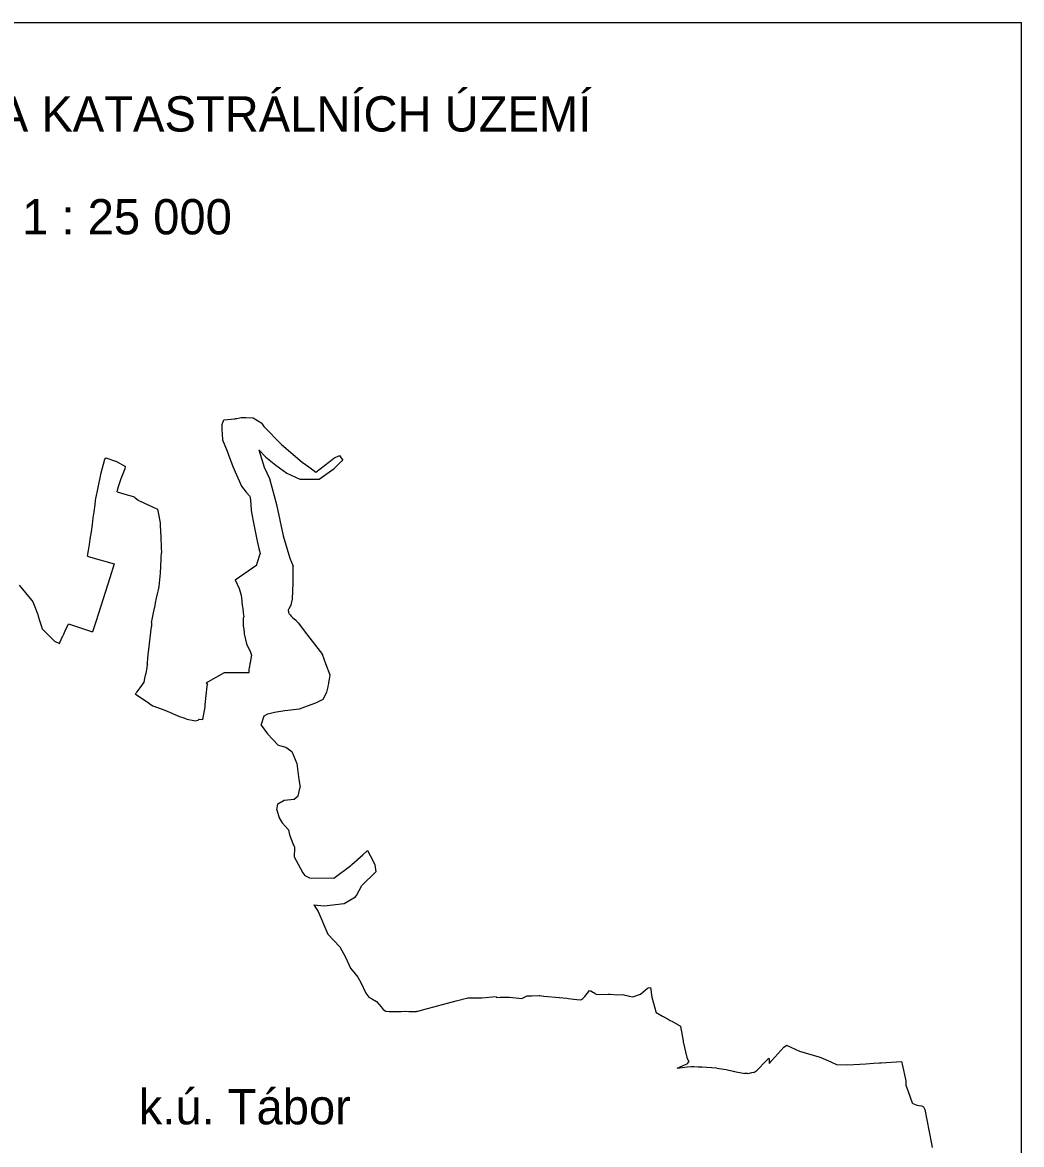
# Model space of a CAD drawing. Extents: x -738519 to -733269, y -1123734 to -1116309.
# Drawn here: x -736104 to -733269, y -1119491 to -1116309 of the extents above; entities that cross this region are included whole.
import ezdxf

# ---------------------------------------------------------------- set-up
doc = ezdxf.new("R2010")
doc.units = 0
doc.layers.add('Implicitní', color=7, linetype='Continuous')
doc.layers.add('Vrstva 13', color=7, linetype='Continuous')

msp = doc.modelspace()

# ---------------------------------------------------------------- linework, layer by layer
at = {"layer": 'Implicitní'}
for p in [(-738519, -1116308.5), (-733269, -1123733.5)]:
    msp.add_line(p, (-733269, -1116308.5), dxfattribs=at)
at = {"layer": 'Vrstva 13'}
for p, q in [((-735538, -1117449.6), (-735536.3, -1117445.8)), ((-735536.3, -1117445.8), (-735531.8, -1117435.8)), ((-735531.8, -1117435.8), (-735500.6, -1117432.4)), ((-735500.6, -1117432.4), (-735498.8, -1117432.2)), ((-735498.8, -1117432.2), (-735495.5, -1117431.5)), ((-735495.5, -1117431.5), (-735482.6, -1117428.8)), ((-735482.6, -1117428.8), (-735469.8, -1117429.1)), ((-735469.8, -1117429.1), (-735448.8, -1117429.6)), ((-735448.8, -1117429.6), (-735424.7, -1117445.2)), ((-735424.7, -1117445.2), (-735423.9, -1117445.7)), ((-735423.9, -1117445.7), (-735418.9, -1117454.7)), ((-735538, -1117449.6), (-735537.4, -1117462.1)), ((-735537.4, -1117462.1), (-735536.7, -1117476.9)), ((-735536.7, -1117476.9), (-735536.2, -1117491.2)), ((-735418.9, -1117454.7), (-735368.5, -1117505.7)), ((-735536.2, -1117491.2), (-735536.1, -1117492.6)), ((-735536.1, -1117492.6), (-735522.6, -1117524.5)), ((-735368.5, -1117505.7), (-735309.8, -1117556.1)), ((-735522.6, -1117524.5), (-735518.6, -1117535.3)), ((-735518.6, -1117535.3), (-735506.5, -1117567.8)), ((-735432.7, -1117520.9), (-735413, -1117541.5)), ((-735432.7, -1117520.9), (-735418.1, -1117569.6)), ((-735413, -1117541.5), (-735384.9, -1117564.7)), ((-735220.3, -1117544.8), (-735203.6, -1117536.7)), ((-735203.6, -1117536.7), (-735199.9, -1117542.2)), ((-735199.9, -1117542.2), (-735194.6, -1117549.8)), ((-735880, -1117586.3), (-735870.1, -1117546.9)), ((-735870.1, -1117546.9), (-735866.6, -1117543.2)), ((-735866.6, -1117543.2), (-735864.4, -1117544)), ((-735864.4, -1117544), (-735842.5, -1117551.7)), ((-735842.5, -1117551.7), (-735839.5, -1117552.8)), ((-735839.5, -1117552.8), (-735839, -1117553.1)), ((-735839, -1117553.1), (-735810.9, -1117568.3)), ((-735823.6, -1117602), (-735812.1, -1117573.4)), ((-735812.1, -1117573.4), (-735810.9, -1117568.3)), ((-735506.5, -1117567.8), (-735482.4, -1117624.2)), ((-735418.1, -1117569.6), (-735403, -1117602.4)), ((-735384.9, -1117564.7), (-735353.2, -1117586.5)), ((-735309.8, -1117556.1), (-735291.2, -1117569.4)), ((-735291.2, -1117569.4), (-735279.9, -1117577.4)), ((-735270.7, -1117584), (-735234.5, -1117555.8)), ((-735261.6, -1117603.6), (-735219, -1117573.5)), ((-735234.5, -1117555.8), (-735220.3, -1117544.8)), ((-735219, -1117573.5), (-735207.1, -1117561.9)), ((-735207.1, -1117561.9), (-735197.3, -1117552.4)), ((-735197.3, -1117552.4), (-735194.6, -1117549.8)), ((-735889.7, -1117632.3), (-735880, -1117586.3)), ((-735831.4, -1117624.9), (-735823.6, -1117602)), ((-735403, -1117602.4), (-735382.4, -1117675.7)), ((-735353.2, -1117586.5), (-735316.6, -1117603.8)), ((-735316.6, -1117603.8), (-735307, -1117603.8)), ((-735307, -1117603.8), (-735261.6, -1117603.6)), ((-735279.9, -1117577.4), (-735270.7, -1117584)), ((-735894.5, -1117655.3), (-735889.7, -1117632.3)), ((-735835.2, -1117639.7), (-735834, -1117634.8)), ((-735834, -1117634.8), (-735831.4, -1117624.9)), ((-735482.4, -1117624.2), (-735469, -1117640.4)), ((-735897.6, -1117676.3), (-735894.9, -1117656.9)), ((-735894.9, -1117656.9), (-735894.5, -1117655.3)), ((-735835.2, -1117639.7), (-735806.5, -1117648.3)), ((-735806.5, -1117648.3), (-735799, -1117650.5)), ((-735799, -1117650.5), (-735786.9, -1117654.2)), ((-735786.9, -1117654.2), (-735785.3, -1117655.4)), ((-735785.3, -1117655.4), (-735784.5, -1117656)), ((-735784.5, -1117656), (-735783.7, -1117656.7)), ((-735783.7, -1117656.7), (-735775.8, -1117662.8)), ((-735775.8, -1117662.8), (-735774, -1117664.2)), ((-735774, -1117664.2), (-735771.4, -1117665.5)), ((-735771.4, -1117665.5), (-735720.4, -1117689.3)), ((-735469, -1117640.4), (-735459.8, -1117651.6)), ((-735459.8, -1117651.6), (-735457.3, -1117654.6)), ((-735457.3, -1117654.6), (-735456, -1117674.6)), ((-735902.4, -1117713.4), (-735900.4, -1117696.6)), ((-735900.4, -1117696.6), (-735897.6, -1117676.3)), ((-735720.4, -1117689.3), (-735718.5, -1117699)), ((-735718.5, -1117699), (-735712.9, -1117727.7)), ((-735456, -1117674.6), (-735454.9, -1117692.6)), ((-735454.9, -1117692.6), (-735448.6, -1117723.2)), ((-735382.4, -1117675.7), (-735363.9, -1117764.3)), ((-735907.8, -1117753.4), (-735905, -1117732.5)), ((-735905, -1117732.5), (-735902.4, -1117713.4)), ((-735712.9, -1117727.7), (-735712.6, -1117735.2)), ((-735448.6, -1117723.2), (-735437.2, -1117779.4)), ((-735910.9, -1117774.2), (-735907.8, -1117753.4)), ((-735712.6, -1117735.2), (-735711, -1117768)), ((-735363.9, -1117764.3), (-735344.8, -1117828.2)), ((-735915.9, -1117806.1), (-735913.3, -1117789.1)), ((-735913.3, -1117789.1), (-735910.9, -1117774.2)), ((-735711, -1117768), (-735709.5, -1117797.6)), ((-735437.2, -1117779.4), (-735436.3, -1117783.9)), ((-735436.3, -1117783.9), (-735432.4, -1117800.5)), ((-735918.7, -1117822.6), (-735915.9, -1117806.1)), ((-735918.7, -1117822.6), (-735910.8, -1117824.9)), ((-735910.8, -1117824.9), (-735843.1, -1117844.5)), ((-735709.7, -1117829.9), (-735709.5, -1117826.1)), ((-735709.5, -1117797.6), (-735708.8, -1117813.2)), ((-735709.5, -1117826.1), (-735708.8, -1117813.2)), ((-735437.3, -1117842.6), (-735429.2, -1117816.2)), ((-735432.4, -1117800.5), (-735430.8, -1117807.6)), ((-735430.8, -1117807.6), (-735429, -1117815.3)), ((-735429.2, -1117816.2), (-735429, -1117815.3)), ((-735344.8, -1117828.2), (-735335, -1117850.9)), ((-735843.1, -1117844.5), (-735855.5, -1117883.4)), ((-735712.1, -1117870.6), (-735709.7, -1117829.9)), ((-735500, -1117889.8), (-735438.6, -1117846.9)), ((-735438.6, -1117846.9), (-735437.3, -1117842.6)), ((-735335.2, -1117898.2), (-735335, -1117850.9)), ((-735855.5, -1117883.4), (-735894.5, -1118005.9)), ((-735715.8, -1117908.2), (-735712.1, -1117870.6)), ((-735500, -1117889.8), (-735488.2, -1117913.7)), ((-736113, -1117904.8), (-736077.2, -1117948.2)), ((-735720.2, -1117928.8), (-735717.9, -1117918)), ((-735717.9, -1117918), (-735715.8, -1117908.2)), ((-735488.2, -1117913.7), (-735486.6, -1117920.3)), ((-735486.6, -1117920.3), (-735483.4, -1117933.4)), ((-735337.2, -1117944.5), (-735335.2, -1117898.2)), ((-736077.2, -1117948.2), (-736074.2, -1117951.8)), ((-736074.2, -1117951.8), (-736068.7, -1117965.7)), ((-735727.4, -1117962.2), (-735725.8, -1117955.2)), ((-735725.8, -1117955.2), (-735722.9, -1117941.7)), ((-735722.9, -1117941.7), (-735720.2, -1117928.8)), ((-735483.4, -1117933.4), (-735481.4, -1117949)), ((-735481.4, -1117949), (-735480.9, -1117952.9)), ((-735480.9, -1117952.9), (-735479.1, -1117966.8)), ((-735339.7, -1117956.9), (-735337.2, -1117944.5)), ((-736068.7, -1117965.7), (-736062, -1117982.7)), ((-736062, -1117982.7), (-736059.9, -1117988.1)), ((-735735.7, -1118001.6), (-735730.8, -1117978.8)), ((-735730.8, -1117978.8), (-735727.4, -1117962.2)), ((-735479.1, -1117966.8), (-735478.6, -1117970.9)), ((-735478.6, -1117970.9), (-735477.1, -1117983.4)), ((-735477.1, -1117983.4), (-735475.8, -1117994.3)), ((-735349.1, -1117978.3), (-735348.4, -1117974.3)), ((-735349.1, -1117978.3), (-735348.3, -1117982.3)), ((-735348.4, -1117974.3), (-735346.7, -1117970.4)), ((-735348.3, -1117982.3), (-735346.4, -1117985.8)), ((-735346.7, -1117970.4), (-735342.7, -1117964.5)), ((-735346.4, -1117985.8), (-735344, -1117989.2)), ((-735342.7, -1117964.5), (-735341, -1117960.9)), ((-735341, -1117960.9), (-735339.7, -1117956.9)), ((-736059.9, -1117988.1), (-736058.5, -1117992.7)), ((-736058.5, -1117992.7), (-736053.8, -1118007.6)), ((-736053.8, -1118007.6), (-736050.1, -1118019.5)), ((-736050.1, -1118019.5), (-736047.2, -1118028.9)), ((-735982.1, -1118034), (-735972.7, -1118014)), ((-735972.7, -1118014), (-735904.4, -1118036.8)), ((-735894.5, -1118005.9), (-735904.4, -1118036.8)), ((-735737.8, -1118010.9), (-735735.7, -1118001.6)), ((-735737.8, -1118010.9), (-735737.7, -1118022.1)), ((-735476.7, -1118020.2), (-735476, -1117999.6)), ((-735476, -1117999.6), (-735475.8, -1117994.3)), ((-735344, -1117989.2), (-735341.2, -1117992.2)), ((-735341.2, -1117992.2), (-735336.3, -1117997.1)), ((-735336.3, -1117997.1), (-735328.5, -1118003.4)), ((-735328.5, -1118003.4), (-735321.3, -1118011.2)), ((-735321.3, -1118011.2), (-735309, -1118027.8)), ((-736047.2, -1118028.9), (-736032.3, -1118043.8)), ((-736032.3, -1118043.8), (-736025.1, -1118051.1)), ((-736025.1, -1118051.1), (-736017.4, -1118058.8)), ((-735991.4, -1118054.2), (-735990.1, -1118051.3)), ((-735990.1, -1118051.3), (-735986.5, -1118043.6)), ((-735986.5, -1118043.6), (-735982.1, -1118034)), ((-735743.4, -1118070.1), (-735737.7, -1118022.1)), ((-735476.8, -1118022.6), (-735476.7, -1118020.2)), ((-735476.8, -1118022.6), (-735474.6, -1118039.2)), ((-735474.6, -1118039.2), (-735474.2, -1118042.6)), ((-735474.2, -1118042.6), (-735467.8, -1118071.1)), ((-735309, -1118027.8), (-735304.1, -1118034.4)), ((-735304.1, -1118034.4), (-735288.4, -1118055.3)), ((-736017.4, -1118058.8), (-736012.6, -1118063.3)), ((-736012.6, -1118063.3), (-735998.7, -1118069.7)), ((-735998.7, -1118069.7), (-735991.4, -1118054.2)), ((-735745.8, -1118094), (-735744.3, -1118079.1)), ((-735744.3, -1118079.1), (-735743.4, -1118070.1)), ((-735467.8, -1118071.1), (-735456.6, -1118094.3)), ((-735288.4, -1118055.3), (-735252.6, -1118101.6)), ((-735747.9, -1118115.5), (-735747.5, -1118110.5)), ((-735747.5, -1118110.5), (-735746.9, -1118104.4)), ((-735746.9, -1118104.4), (-735746.6, -1118101.6)), ((-735746.6, -1118101.6), (-735745.8, -1118094)), ((-735456.7, -1118124.6), (-735453.6, -1118107)), ((-735456.6, -1118094.3), (-735454.5, -1118100.6)), ((-735454.5, -1118100.6), (-735453.2, -1118104.8)), ((-735453.6, -1118107), (-735453.2, -1118104.8)), ((-735242.6, -1118127.5), (-735252.6, -1118101.6)), ((-735752.9, -1118154.2), (-735750.1, -1118139.1)), ((-735750.1, -1118139.1), (-735749.4, -1118135.8)), ((-735749.4, -1118135.8), (-735749.1, -1118131.4)), ((-735749.3, -1118128.8), (-735749, -1118125.9)), ((-735749.3, -1118128.8), (-735749.1, -1118131.4)), ((-735749, -1118125.9), (-735748.4, -1118121.3)), ((-735748.4, -1118121.3), (-735747.9, -1118115.5)), ((-735460.3, -1118148.4), (-735460.2, -1118146.8)), ((-735460.2, -1118146.8), (-735460.1, -1118143.4)), ((-735460.1, -1118143.4), (-735459.2, -1118138.6)), ((-735459.2, -1118138.6), (-735458.7, -1118135.6)), ((-735458.7, -1118135.6), (-735457.3, -1118127.8)), ((-735457.3, -1118127.8), (-735457, -1118126.1)), ((-735457, -1118126.1), (-735456.7, -1118124.6)), ((-735230, -1118159.9), (-735242.6, -1118127.5)), ((-735757.7, -1118179.4), (-735755.9, -1118169.8)), ((-735755.9, -1118169.8), (-735754, -1118159.6)), ((-735754, -1118159.6), (-735752.9, -1118154.2)), ((-735579, -1118179.6), (-735575.2, -1118177.6)), ((-735575.2, -1118177.6), (-735530.2, -1118152.8)), ((-735530.2, -1118152.8), (-735498.9, -1118152.8)), ((-735498.9, -1118152.8), (-735460.5, -1118152.4)), ((-735460.5, -1118152.4), (-735460.3, -1118148.4)), ((-735233.9, -1118180.3), (-735232.4, -1118172.6)), ((-735232.4, -1118172.6), (-735232.1, -1118170.9)), ((-735232.1, -1118170.9), (-735230, -1118159.9)), ((-735783, -1118213.7), (-735780.4, -1118210.2)), ((-735780.4, -1118210.2), (-735777.9, -1118206.9)), ((-735777.9, -1118206.9), (-735772.5, -1118199.5)), ((-735772.5, -1118199.5), (-735769.5, -1118195.4)), ((-735769.5, -1118195.4), (-735757.7, -1118179.4)), ((-735584.7, -1118244.2), (-735579.7, -1118191.2)), ((-735582.7, -1118181.7), (-735579, -1118179.6)), ((-735582.7, -1118181.7), (-735578.1, -1118186.5)), ((-735579.7, -1118191.2), (-735578.1, -1118186.5)), ((-735250.1, -1118228.3), (-735239.6, -1118207.9)), ((-735239.6, -1118207.9), (-735236.4, -1118192.9)), ((-735236.4, -1118192.9), (-735236, -1118191.2)), ((-735236, -1118191.2), (-735234.5, -1118183.4)), ((-735234.5, -1118183.4), (-735233.9, -1118180.3)), ((-735783, -1118213.7), (-735747, -1118237.9)), ((-735747, -1118237.9), (-735738.4, -1118243.7)), ((-735295.1, -1118247), (-735271.5, -1118238.8)), ((-735271.5, -1118238.8), (-735267.4, -1118236.8)), ((-735267.4, -1118236.8), (-735265.8, -1118236)), ((-735265.8, -1118236), (-735250.1, -1118228.3)), ((-735738.4, -1118243.7), (-735733.5, -1118246.9)), ((-735733.5, -1118246.9), (-735699.1, -1118259.2)), ((-735699.1, -1118259.2), (-735658.2, -1118277.1)), ((-735591.7, -1118285.7), (-735585.2, -1118249.4)), ((-735585.2, -1118249.4), (-735584.7, -1118244.2)), ((-735417.5, -1118275.1), (-735407.2, -1118269.7)), ((-735407.2, -1118269.7), (-735388.3, -1118264.6)), ((-735388.3, -1118264.6), (-735358.7, -1118259.9)), ((-735358.7, -1118259.9), (-735317.2, -1118255.1)), ((-735317.2, -1118255.1), (-735295.1, -1118247)), ((-735658.2, -1118277.1), (-735645.7, -1118281.3)), ((-735645.7, -1118281.3), (-735636.8, -1118284.3)), ((-735636.8, -1118284.3), (-735617.1, -1118288.6)), ((-735617.1, -1118288.6), (-735613.7, -1118289.4)), ((-735613.7, -1118289.4), (-735609.6, -1118288.8)), ((-735609.6, -1118288.8), (-735605.4, -1118287.6)), ((-735605.4, -1118287.6), (-735602.5, -1118284.6)), ((-735602.5, -1118284.6), (-735591.7, -1118285.7)), ((-735426.7, -1118301.5), (-735417.5, -1118275.1)), ((-735426.7, -1118301.5), (-735407.9, -1118326.2)), ((-735407.9, -1118326.2), (-735377.6, -1118358)), ((-735377.6, -1118358), (-735356.3, -1118364.5)), ((-735356.3, -1118364.5), (-735339.1, -1118376.7)), ((-735339.1, -1118376.7), (-735334.3, -1118387.4)), ((-735334.3, -1118387.4), (-735324.8, -1118410.6)), ((-735324.8, -1118410.6), (-735319.6, -1118455.4)), ((-735319.6, -1118455.4), (-735316, -1118477.9)), ((-735320.8, -1118502), (-735316, -1118477.9)), ((-735382.2, -1118541.6), (-735378.5, -1118525.3)), ((-735378.5, -1118525.3), (-735360.7, -1118514.2)), ((-735360.7, -1118514.2), (-735332.6, -1118511.8)), ((-735332.6, -1118511.8), (-735320.8, -1118502)), ((-735382.2, -1118541.6), (-735375.3, -1118564.5)), ((-735375.3, -1118564.5), (-735366.3, -1118578.7)), ((-735366.3, -1118578.7), (-735348.6, -1118598.4)), ((-735348.6, -1118598.4), (-735346.2, -1118612.5)), ((-735346.2, -1118612.5), (-735336.8, -1118637.8)), ((-735336.8, -1118637.8), (-735331.8, -1118648)), ((-735331.9, -1118650.3), (-735332.6, -1118675.5)), ((-735331.8, -1118648), (-735331.9, -1118650.3)), ((-735332.6, -1118675.5), (-735321.7, -1118695.6)), ((-735169.2, -1118697.2), (-735137.9, -1118669.3)), ((-735137.9, -1118669.3), (-735124.1, -1118657)), ((-735124.1, -1118657), (-735117, -1118671.2)), ((-735117, -1118671.2), (-735104.1, -1118697.1)), ((-735321.7, -1118695.6), (-735308, -1118720.8)), ((-735220.5, -1118736), (-735171.8, -1118699.5)), ((-735171.8, -1118699.5), (-735169.2, -1118697.2)), ((-735140.3, -1118756.2), (-735100.9, -1118718)), ((-735104.1, -1118697.1), (-735103.1, -1118704.6)), ((-735103.1, -1118704.6), (-735100.9, -1118718)), ((-735308, -1118720.8), (-735302, -1118728.4)), ((-735302, -1118728.4), (-735288.9, -1118735.2)), ((-735288.9, -1118735.2), (-735220.5, -1118736)), ((-735156.2, -1118784.5), (-735140.3, -1118756.2)), ((-735276.7, -1118810.9), (-735247.4, -1118814.5)), ((-735276.7, -1118810.9), (-735269.9, -1118821.8)), ((-735247.4, -1118814.5), (-735190.3, -1118807.3)), ((-735190.3, -1118807.3), (-735158.3, -1118788.3)), ((-735158.3, -1118788.3), (-735156.2, -1118784.5)), ((-735269.9, -1118821.8), (-735264.9, -1118829.8)), ((-735264.9, -1118829.8), (-735237, -1118894.2)), ((-735237, -1118894.2), (-735203.1, -1118930.7)), ((-735203.1, -1118930.7), (-735186.5, -1118959.4)), ((-735186.5, -1118959.4), (-735172.7, -1118991.1)), ((-735172.7, -1118991.1), (-735159.5, -1119007)), ((-735159.5, -1119007), (-735152.1, -1119016.5)), ((-735152.1, -1119016.5), (-735143.9, -1119031.3)), ((-735143.9, -1119031.3), (-735129.2, -1119061.5)), ((-735129.2, -1119061.5), (-735124, -1119069.4)), ((-735124, -1119069.4), (-735120.6, -1119072.8)), ((-734686.6, -1119077.5), (-734671.9, -1119069.9)), ((-734671.9, -1119069.9), (-734658.4, -1119069.3)), ((-734658.4, -1119069.3), (-734638, -1119068.3)), ((-734638, -1119068.3), (-734635.6, -1119068.9)), ((-734635.6, -1119068.9), (-734629.7, -1119069.8)), ((-734629.7, -1119069.8), (-734624.1, -1119070.8)), ((-734508, -1119071.8), (-734494.4, -1119054.1)), ((-734494.4, -1119054.1), (-734491.1, -1119056.1)), ((-734483.2, -1119060.9), (-734491.1, -1119056.1)), ((-734482.4, -1119061.4), (-734483.2, -1119060.9)), ((-734480, -1119063), (-734482.4, -1119061.4)), ((-734480, -1119063), (-734473.8, -1119065.8)), ((-734473.8, -1119065.8), (-734441.6, -1119064.7)), ((-734441.6, -1119064.7), (-734436.1, -1119065)), ((-734436.1, -1119065), (-734416.5, -1119066.7)), ((-734416.5, -1119066.7), (-734400.7, -1119065.9)), ((-734400.7, -1119065.9), (-734397.6, -1119066.8)), ((-734397.6, -1119066.8), (-734394.9, -1119067.5)), ((-734394.9, -1119067.5), (-734388.8, -1119068.6)), ((-734388.8, -1119068.6), (-734381.8, -1119070.1)), ((-734381.8, -1119070.1), (-734371.7, -1119072.1)), ((-734371.7, -1119072.1), (-734350, -1119064.5)), ((-734350, -1119064.5), (-734330, -1119047.3)), ((-734330, -1119047.3), (-734327.6, -1119046.8)), ((-734327.6, -1119046.8), (-734321.7, -1119045.6)), ((-734321.7, -1119045.6), (-734317.7, -1119072.9)), ((-735120.6, -1119072.8), (-735113.6, -1119077)), ((-735113.6, -1119077), (-735110.1, -1119079)), ((-735110.1, -1119079), (-735099.1, -1119085.4)), ((-735099.1, -1119085.4), (-735086, -1119101.1)), ((-735086, -1119101.1), (-735080.2, -1119108.2)), ((-734965.1, -1119108.2), (-734873.3, -1119084.1)), ((-734873.3, -1119084.1), (-734840.1, -1119075.4)), ((-734840.1, -1119075.4), (-734800.5, -1119074.9)), ((-734800.5, -1119074.9), (-734759.2, -1119071.5)), ((-734759.2, -1119071.5), (-734758.4, -1119074)), ((-734758.4, -1119074), (-734748.2, -1119073.3)), ((-734748.2, -1119073.3), (-734726.2, -1119073.5)), ((-734726.2, -1119073.5), (-734721.7, -1119073.5)), ((-734721.7, -1119073.5), (-734686.6, -1119077.5)), ((-734624.1, -1119070.8), (-734579.8, -1119074.1)), ((-734579.8, -1119074.1), (-734558.9, -1119076.1)), ((-734558.9, -1119076.1), (-734553.9, -1119076.7)), ((-734553.9, -1119076.7), (-734538.8, -1119078.6)), ((-734538.8, -1119078.6), (-734530.6, -1119079.7)), ((-734530.6, -1119079.7), (-734519.3, -1119081.1)), ((-734519.3, -1119081.1), (-734513.9, -1119076.6)), ((-734513.9, -1119076.6), (-734508, -1119071.8)), ((-734317.7, -1119072.9), (-734308.3, -1119107.6)), ((-735080.2, -1119108.2), (-735072.6, -1119112.7)), ((-735072.6, -1119112.7), (-735063.4, -1119113.9)), ((-735063.4, -1119113.9), (-735054.7, -1119113.9)), ((-735054.7, -1119113.9), (-735029.4, -1119114.1)), ((-735029.4, -1119114.1), (-735016.9, -1119113)), ((-735016.9, -1119113), (-735007.4, -1119113.8)), ((-735007.4, -1119113.8), (-734988.9, -1119113.8)), ((-734988.9, -1119113.8), (-734987.2, -1119113.8)), ((-734987.2, -1119113.8), (-734985.7, -1119113.8)), ((-734985.7, -1119113.8), (-734983.4, -1119113)), ((-734983.4, -1119113), (-734981.7, -1119112.6)), ((-734981.7, -1119112.6), (-734965.1, -1119108.2)), ((-734308.3, -1119107.6), (-734307.2, -1119111.8)), ((-734307.2, -1119111.8), (-734305.7, -1119117.2)), ((-734305.7, -1119117.2), (-734287.2, -1119127.4)), ((-734287.2, -1119127.4), (-734283.9, -1119129.3)), ((-734283.9, -1119129.3), (-734271.5, -1119136.1)), ((-734271.5, -1119136.1), (-734265.9, -1119139.2)), ((-734265.9, -1119139.2), (-734261.2, -1119141.7)), ((-734261.2, -1119141.7), (-734236.4, -1119155.4)), ((-734236.4, -1119155.4), (-734236.3, -1119156.2)), ((-734236.3, -1119156.2), (-734229.3, -1119196.8)), ((-734229.3, -1119196.8), (-734229, -1119198.9)), ((-734229, -1119198.9), (-734228.8, -1119199.9)), ((-734228.8, -1119199.9), (-734218.6, -1119244.7)), ((-733977.4, -1119252.5), (-733943.7, -1119215)), ((-733943.7, -1119215), (-733936.4, -1119210.2)), ((-733936.4, -1119210.2), (-733935.5, -1119209.6)), ((-733935.5, -1119209.6), (-733898.9, -1119226.6)), ((-733898.9, -1119226.6), (-733844.1, -1119242.3)), ((-734218.6, -1119244.7), (-734213.1, -1119256.9)), ((-734217, -1119261.5), (-734213.1, -1119256.9)), ((-734018, -1119279.1), (-733994.4, -1119255.2)), ((-733994.4, -1119255.2), (-733991.7, -1119252.4)), ((-733991.7, -1119252.4), (-733985.6, -1119246.4)), ((-733985.6, -1119246.4), (-733985.4, -1119249.7)), ((-733985.4, -1119249.7), (-733985, -1119257.8)), ((-733985, -1119257.8), (-733984.8, -1119261.2)), ((-733984.8, -1119261.2), (-733977.4, -1119252.5)), ((-733844.1, -1119242.3), (-733838.5, -1119244.6)), ((-733838.5, -1119244.6), (-733810.5, -1119257.1)), ((-733810.5, -1119257.1), (-733793.8, -1119264.7)), ((-733710.3, -1119262), (-733688.8, -1119260.8)), ((-733688.8, -1119260.8), (-733672.3, -1119259.8)), ((-733672.3, -1119259.8), (-733667.7, -1119259.5)), ((-733667.7, -1119259.5), (-733609.6, -1119255.7)), ((-733609.6, -1119255.7), (-733607.9, -1119262.9)), ((-734246.1, -1119274.3), (-734231.3, -1119268)), ((-734246.1, -1119274.3), (-734217.2, -1119271)), ((-734231.3, -1119268), (-734227.4, -1119266.3)), ((-734227.4, -1119266.3), (-734217.7, -1119262.4)), ((-734217.7, -1119262.4), (-734217, -1119261.5)), ((-734217.2, -1119271), (-734205.3, -1119269.7)), ((-734205.3, -1119269.7), (-734201.3, -1119270)), ((-734201.3, -1119270), (-734198.3, -1119270.1)), ((-734198.3, -1119270.1), (-734186.4, -1119270.6)), ((-734186.4, -1119270.6), (-734177.6, -1119271.2)), ((-734177.6, -1119271.2), (-734175.6, -1119271.4)), ((-734133.7, -1119274.6), (-734175.6, -1119271.4)), ((-734133.7, -1119274.6), (-734107.4, -1119278.4)), ((-734107.4, -1119278.4), (-734087.5, -1119283)), ((-734087.5, -1119283), (-734086.1, -1119283.3)), ((-734086.1, -1119283.3), (-734082.9, -1119283.9)), ((-734082.9, -1119283.9), (-734058.8, -1119288.8)), ((-734058.8, -1119288.8), (-734054.8, -1119289.3)), ((-734046.2, -1119290.2), (-734054.8, -1119289.3)), ((-734044.4, -1119290.4), (-734046.2, -1119290.2)), ((-734035.2, -1119288.2), (-734044.4, -1119290.4)), ((-734028.5, -1119286.6), (-734035.2, -1119288.2)), ((-734028.5, -1119286.6), (-734020.3, -1119281.5)), ((-734020.3, -1119281.5), (-734018, -1119279.1)), ((-733793.8, -1119264.7), (-733762.2, -1119265.3)), ((-733762.2, -1119265.3), (-733710.3, -1119262)), ((-733607.9, -1119262.9), (-733597.2, -1119310.7)), ((-733597.2, -1119310.7), (-733597.1, -1119323)), ((-733597.1, -1119323), (-733590.7, -1119340.7)), ((-733590.7, -1119340.7), (-733579.6, -1119372.6)), ((-733579.6, -1119372.6), (-733577.1, -1119375.1)), ((-733577.1, -1119375.1), (-733572.3, -1119376.9)), ((-733572.3, -1119376.9), (-733567.9, -1119378.6)), ((-733567.9, -1119378.6), (-733565.7, -1119379.7)), ((-733565.7, -1119379.7), (-733553.3, -1119381.5)), ((-733553.3, -1119381.5), (-733547.1, -1119384.7)), ((-733547.1, -1119384.7), (-733543.5, -1119392)), ((-733543.5, -1119392), (-733537.5, -1119421.6)), ((-733537.5, -1119421.6), (-733524.7, -1119489.6)), ((-733524.7, -1119489.6), (-733522.7, -1119500))]:
    msp.add_line(p, q, dxfattribs=at)

# ---------------------------------------------------------------- texts
at = {"layer": 'Implicitní'}
for s, p in [('PŘEHLEDKA KATASTRÁLNÍCH ÚZEMÍ', (-736897.1, -1116617.9)), ('1 : 25 000', (-736104.3, -1116909.6))]:
    msp.add_text(s, height=100, dxfattribs=at).set_placement(p)
at = {"layer": 'Vrstva 13'}
msp.add_text('k.ú. Tábor', height=100, dxfattribs=at).set_placement((-735773.7, -1119434))

doc.saveas('drawing.dxf')
